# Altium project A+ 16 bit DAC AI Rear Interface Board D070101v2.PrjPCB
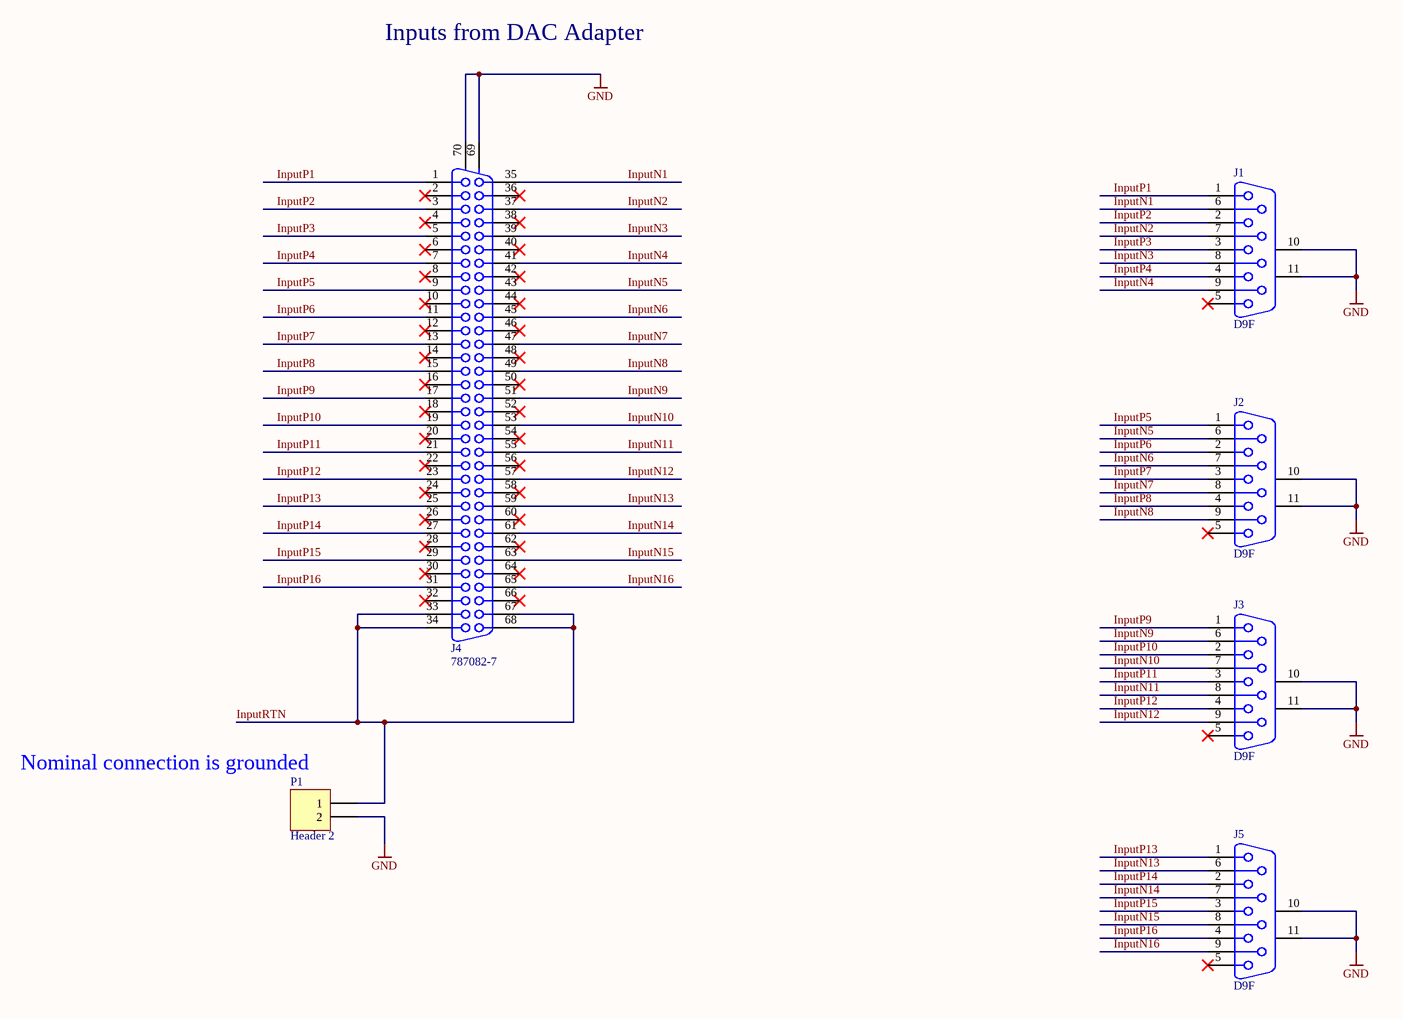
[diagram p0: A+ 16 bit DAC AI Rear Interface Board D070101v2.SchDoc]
1 sheet, 6 parts. Net scope: global (net labels, ports and power ports of the same name join across sheets).
Board file: A+ 16 bit DAC AI Rear Interface Board D070101v2.PcbDoc

## Sheet A+ 16 bit DAC AI Rear Interface Board D070101v2.SchDoc: A+ DAC AI Interface Board
size B; DrawnBy: Dean Schaetzl; Engineer: J. Heefner; DocumentNumber: D070101; Revision: v2; SheetNumber: 1; SheetTotal: 1; PageSetup: Record=PageOptions¦CenterHorizontal=True¦CenterVertical=True¦PrintScale=1.12¦XCorrection=1.00¦YCorrection=1.00¦PrintKind=0¦BorderSize=5000000¦LeftOffset=0¦BottomOffset=0¦Orientation=2¦PaperLength=1000¦PaperWidth=1000¦Scale=100¦PaperSource=15¦PrintQuality=1200¦MediaType=1¦DitherType=10¦PaperKind=Tabloid¦PrintScaleMode=1

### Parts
J1  D9F  [D9F]
J2  D9F  [D9F]
J3  D9F  [D9F]
J4  787082-7  [787082-7]
J5  D9F  [D9F]
P1  Header 2  [HDR1X2]

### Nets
GND: J1.10(MH1) J1.11(MH2) J2.10(MH1) J2.11(MH2) J3.10(MH1) J3.11(MH2) J4.69(MH1) J4.70(MH2) J5.10(MH1) J5.11(MH2) P1.2
InputN1: J1.6 J4.35
InputN2: J1.7 J4.37
InputN3: J1.8 J4.39
InputN4: J1.9 J4.41
InputN5: J2.6 J4.43
InputN6: J2.7 J4.45
InputN7: J2.8 J4.47
InputN8: J2.9 J4.49
InputN9: J3.6 J4.51
InputN10: J3.7 J4.53
InputN11: J3.8 J4.55
InputN12: J3.9 J4.57
InputN13: J4.59 J5.6
InputN14: J4.61 J5.7
InputN15: J4.63 J5.8
InputN16: J4.65 J5.9
InputP1: J1.1 J4.1
InputP2: J1.2 J4.3
InputP3: J1.3 J4.5
InputP4: J1.4 J4.7
InputP5: J2.1 J4.9
InputP6: J2.2 J4.11
InputP7: J2.3 J4.13
InputP8: J2.4 J4.15
InputP9: J3.1 J4.17
InputP10: J3.2 J4.19
InputP11: J3.3 J4.21
InputP12: J3.4 J4.23
InputP13: J4.25 J5.1
InputP14: J4.27 J5.2
InputP15: J4.29 J5.3
InputP16: J4.31 J5.4
InputRTN: J4.33 J4.34 J4.67 J4.68 P1.1

Not connected (* = marked no-connect by the designer): J1 5*; J2 5*; J3 5*; J4 2* 4* 6* 8* 10* 12* 14* 16* 18* 20* 22* 24* 26* 28* 30* 32* 36* 38* 40* 42* 44* 46* 48* 50* 52* 54* 56* 58* 60* 62* 64* 66*; J5 5*

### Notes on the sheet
- Inputs from DAC Adapter
- (near P1) Nominal connection is grounded

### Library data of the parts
J1-J3 J5 = D9F: 9 Position D-Sub Receptacle, Female Sockets Connector; Manufacturer: TE Connectivity; Manufacturer Part Number: 5747150-7; Plating: Tin; Body Material: Metal; Voltage Rating: 125V; Current Rating: 6A; Max Voltage Rating (DC): 250.25kV; Number of Positions: 9; Number of Ports: 1; Max Supply Voltage (AC): 250V; Mating Connector Lock: Yes (With); PCB Mount Retention: With; PCB Mounting Orientation: Vertical; Preloaded: Yes; Sealable: No (Without); Pitch: 0.108inch; PCB Thickness: 2.36mm; Contact Post Length: 0.125inch; Hole Diameter: 0.12inch; Approvals: UL
J4 = D68F 90deg: 68 Position D-Type Receptacle, Female Sockets Connector; Manufacturer: TE Connectivity; Manufacturer Part Number: 7870827; Plating: Bright,Copper; Voltage Rating: 30V; Current Rating: 1A; Number of Positions: 68; Connector Type: Receptacle,Connector; Number of Ports: 1; Shielding: Shielded; Mating Alignment: No (Without); Mating Connector Lock: Yes (With); PCB Mount Retention: With; PCB Mounting Orientation: Right Angle; Pitch: 0.05inch; PCB Thickness: 1.57mm; Contact Post Length: 0.1inch; Hole Diameter: 0.109inch; Approvals: UL
P1 = Header 2: Connector Header Through Hole 2 position 0.100" (2.54mm); Manufacturer: Molex; Number of Positions: 2; Gender: Male; Contact Resistance: 10mR; Max Current Rating: 4A; Voltage Rating: 250V; Insulation Resistance: 500GR; Approvals: UL,CSA; Glow Wire Compliant: Non-compliant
